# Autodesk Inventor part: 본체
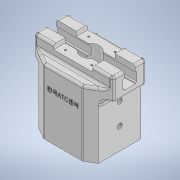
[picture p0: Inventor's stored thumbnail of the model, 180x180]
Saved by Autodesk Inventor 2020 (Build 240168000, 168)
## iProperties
Created: 2023-05
Part Number: 본체
Material: 일반
Document SubType Name: Modeling
Designer: oem
Density: 1 g/cm^3
Appearance: 기본값
Author: oem
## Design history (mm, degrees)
sketch "스케치1"
  geometry: L1 (0, 0)-(126.476, 0); L2 (25.019, -35)-(51, -20); L3 (51, -20)-(51, 20); L4 (25.019, 35)-(51, 20); L5 (0, 0)-(0, -35); L6 (0, -35)-(25.019, -35); L7 (0, 0)-(-126.476, 0); L8 (-25.019, -35)-(-51, -20); L9 (-51, -20)-(-51, 20); L10 (-25.019, 35)-(-51, 20); L11 (0, -35)-(-25.019, -35); L12 (25.019, 35)-(-25.019, 35)
  constraints: 24 end point, 6 symmetric about line, 2 horizontal, 1 vertical
  dimensions: "d7" = 30 deg angle of L1 L2; "d9" = 40 distance of L2.end L3.end; "d10" = 20 distance from line of L1 L2.end; "d11" = 20 distance from line of L1 L3.end; "d33" = 35 distance from line of L1 L2.start; "d34" = 51 distance from line of L1.start L3; "d39" = 35 distance of L1.start L5.end
extrude "돌출1" new body sketch "스케치1" distance "d12" = 29; taper "d13" = 0 deg
sketch "스케치5"
  geometry: L1 (51, 20)-(25.019, 35) reference; L2 (25.019, 35)-(-25.019, 35) reference; L3 (-25.019, 35)-(-51, 20) reference; L4 (-51, -20)-(-25.019, -35) reference; L5 (-25.019, -35)-(25.019, -35) reference; L6 (25.019, -35)-(51, -20) reference; L7 (74.204, -22)-(-74.204, -22); L8 (-74.204, -22)-(-74.204, 22); L9 (-74.204, 22)-(74.204, 22); L10 (74.204, 22)-(74.204, -22); L11 (74.204, -22)-(-74.204, 22); L12 (-74.204, -22)-(74.204, 22); 5 further points
  constraints: 12 end point, 2 midpoint, 2 parallel, 1 horizontal, 1 perpendicular
  dimensions: "d40" = 44 distance of L7.end L8.end; "d41" = 148.40766 distance of L8.end L9.end
extrude "돌출4" cut sketch "스케치5" distance "d42" = 15; taper "d43" = 0 deg
sketch "스케치6"
  geometry: L1 (0, 29)-(40, 29) reference; L2 (20, 29)-(12.8, 29); L3 (12.8, 29)-(12.8, 21.482); L4 (20, 21)-(11, 21); L5 (11, 21)-(11, 10); L6 (11, 21)-(12.8, 21.482); L7 (11, 21)-(14.021, 21); L8 (20, 8)-(12.8, 8); L9 (11, 15.5)-(18.681, 15.5); L10 (11, 10)-(12.8, 9.518); L11 (12.8, 8)-(12.8, 9.518); L12 (20, 8)-(20, 29); L13 (20, 29)-(27.2, 29); L14 (27.2, 29)-(27.2, 21.482); L15 (29, 21)-(29, 10); L16 (29, 10)-(27.2, 9.518); L17 (20, 8)-(27.2, 8); L18 (29, 21)-(27.2, 21.482); L19 (27.2, 8)-(27.2, 9.518); 1 further point
  constraints: 36 end point, 7 symmetric about line, 4 horizontal, 2 midpoint, 2 vertical, 1 perpendicular, 1 point on line
  dimensions: "d44" = 7.2 distance of L2.start L2.end; "d48" = 8 distance from line of L1 L4.end; "d49" = 11 distance of L4.end L5.end; "d50" = 9 horizontal distance of L4.end L2.start; "d51" = 15 deg angle of L7 L6; "d52" = 7.2 distance of L8.start L8.end; "d53" = 21 distance between parallel lines of L8 L1
extrude "돌출5" cut sketch "스케치6" extent not by distance; stored distance "d54" = 0; taper "d55" = 0 deg
sketch "스케치7"
  geometry: L1 (47.536, 22)-(-47.536, 22) reference; L2 (-25, -22)-(25, -22); L3 (25, -22)-(25, 22); L4 (25, 22)-(-25, 22); L5 (-25, 22)-(-25, -22); L6 (-25, -22)-(25, 22); L7 (25, -22)-(-25, 22); 2 further points
  constraints: 12 end point, 2 midpoint, 2 parallel, 1 horizontal, 1 perpendicular, 1 point on line
  dimensions: "d56" = 50 distance of L4.end L3.end
extrude "돌출6" cut sketch "스케치7" distance "d57" = 6; taper "d58" = 0 deg
sketch "스케치15"
  geometry: L1 (0, 0)-(29, 0); L2 (10.392, -6)-(29, -6); L3 (10.392, 6)-(29, 6); L4 (0, 0)-(0, -29.09); L5 (-10.392, -6)-(-29, -6); L6 (-10.392, 6)-(-29, 6); A1 r 6 centre (29, 0) between (29, -6) and (29, 6); A2 r 6 centre (-29, 0) between (-29, 6) and (-29, -6); A3 r 12 centre (0, 0) between (10.392, 6) and (-10.392, 6); A4 r 12 centre (0, 0) between (-10.392, -6) and (10.392, -6); 1 further point
  constraints: 12 end point, 8 point on circle, 5 symmetric about line, 4 centre point, 2 coincident, 2 parallel, 1 horizontal, 1 vertical, 1 other
  dimensions: "d116" = 29 distance of L1.start L1.end; "d117" = 6 distance between parallel lines of L1 L2; "d118" = 6 distance between parallel lines of L1 L3; "d120" = 6 radius of A1; "d121" = 12 radius of A4; "d122" = 12 radius of A3
extrude "돌출8" cut sketch "스케치15" distance "d114" = 30; taper "d115" = 0 deg
sketch "스케치18"
  geometry: L1 (51, -20)-(25.019, -35) reference; L2 (-25.019, -35)-(-51, -20) reference; L3 (25.019, -35)-(-25.019, -35) reference; L4 (0, 0)-(40, 0); L5 (40, 0)-(40, -26.351); L6 (25.019, -35)-(47.536, -22) reference; L7 (40, -26.351)-(25.019, -35); L8 (0, -35)-(0, 0); L9 (0, -35)-(25.019, -35); L10 (-25.019, -35)-(-38.01, -27.5); L11 (-25.019, -35)-(0, -35); L12 (-25.019, 35)-(0, 35); L13 (-25.019, 35)-(-38.01, 27.5); L14 (0, 35)-(25.019, 35); L15 (40, 26.351)-(25.019, 35); L16 (40, 0)-(40, 26.351); L17 (-51, 20)-(-25.019, 35) reference; L18 (0, 0)-(-40, 0); L19 (-40, 0)-(-40, 26.351); L20 (-38.01, 27.5)-(-40, 26.351); L21 (-40, 0)-(-40, -26.351); L22 (-38.01, -27.5)-(-40, -26.351); A1 r 12 centre (0, 0) between (-10.392, -6) and (10.392, -6) reference; A2 r 12 centre (0, 0) between (10.392, 6) and (-10.392, 6) reference
  constraints: 34 end point, 5 collinear, 3 point on line, 3 symmetric about line, 2 horizontal, 2 midpoint, 2 perpendicular, 2 vertical
  dimensions: "d136" = 40 distance of L4.start L4.end; "d254" = 40 distance of L18.start L18.end
extrude "돌출9" join sketch "스케치18" distance "d138" = 70; taper "d139" = 0 deg
node "작업 평면2"
sketch "스케치26"
  geometry: C1 r 10 at (0, 0); 1 further point
  constraints: 1 centre point, 1 coincident
  dimensions: "d180" = 20 diameter of C1
extrude "돌출10" cut sketch "스케치26" stored distance "d181" = 3.2; taper "d182" = 0 deg
sketch "스케치27"
  geometry: A1 r 12 centre (0, 0) between (9.6, 7.2) and (-9.6, 7.2) reference; 1 further point
  dimensions: "d184" = 17 horizontal distance of A1.centre point (-17, 15); "d185" = 15 vertical distance of A1.centre point (-17, 15)
hole "구멍11" sketch "스케치27" at (-17, 15) diameter "d186" = 2.459; stored, may be unused: countersink angle "d190" = 82 deg, drill point angle "d192" = 118 deg; dims "d187" = 6, "d188" = 3.023, "d189" = 2, "d191" = 8
fillet "모깎기2" dims "d232" = 3
fillet "모깎기3" dims "d233" = 3
fillet "모깎기4" dims "d234" = 3
sketch "스케치31"
  geometry: L1 (25.715, -34.598)-(40, -26.351) reference; L2 (40, -26.351)-(40, 26.351) reference; L3 (40, 26.351)-(25.715, 34.598) reference; L4 (38, 31.43)-(38, -34.903); 2 further points
  constraints: 2 end point, 1 vertical
  dimensions: "d235" = 2 distance between parallel lines of L2 L4
extrude "돌출11" cut sketch "스케치31" distance "d236" = 64; taper "d237" = 0 deg
fillet "모깎기5" dims "d248" = 3
sketch "스케치34"
  geometry: 2 further points
  constraints: 1 coincident
hole "구멍16" sketch "스케치34" at (0, 0) diameter "d255" = 60; stored, may be unused: countersink angle "d259" = 90 deg, drill point angle "d261" = 0 deg; dims "d256" = 9, "d257" = 17.3, "d258" = 2, "d260" = 5.8
sketch "스케치35"
  geometry: C1 r 30 at (0, 0) reference; 2 further points
  constraints: 1 coincident
hole "구멍17" sketch "스케치35" at (0, 0) diameter "d262" = 63; stored, may be unused: countersink angle "d266" = 90 deg, drill point angle "d268" = 0 deg; dims "d263" = 9, "d264" = 17.3, "d265" = 2, "d267" = 2.2
sketch "스케치36"
  geometry: C1 r 30 at (0, 0) reference; 2 further points
  constraints: 1 coincident
hole "구멍18" sketch "스케치36" at (0, 0) diameter "d269" = 60; stored, may be unused: countersink angle "d273" = 90 deg, drill point angle "d275" = 0 deg; dims "d270" = 9, "d271" = 17.3, "d272" = 2, "d274" = 6
sketch "스케치37"
  geometry: C1 r 30 at (0, 0) reference; 2 further points
  constraints: 1 coincident
hole "구멍19" sketch "스케치37" at (0, 0) diameter "d276" = 50; stored, may be unused: countersink angle "d280" = 90 deg, drill point angle "d282" = 0 deg; dims "d277" = 9, "d278" = 17.3, "d279" = 2, "d281" = 45
chamfer "모따기4" distance "d283" = 2; stored, may be unused: second distance "d284" = 2, angle "d285" = 20 deg
sketch "스케치39"
  geometry: C1 r 25 at (0, 0) reference; 2 further points
  constraints: 1 coincident
hole "구멍20" sketch "스케치39" at (0, 0) diameter "d286" = 16; stored, may be unused: countersink angle "d290" = 90 deg, drill point angle "d292" = 0 deg; dims "d287" = 9, "d288" = 17.3, "d289" = 2, "d291" = 45
sketch "스케치40"
  geometry: L1 (55.011, 0)-(0, 0) reference; L2 (-7.494, 81)-(-7.494, 0) reference; 2 further points
  dimensions: "d293" = 28 distance from line of L1 point (27.506, 28); "d294" = 35 distance from line of point (27.506, 28) L2
hole "구멍21" sketch "스케치40" at (27.506, 28) diameter "d295" = 4; stored, may be unused: countersink angle "d299" = 90 deg, drill point angle "d301" = 0 deg; dims "d296" = 9, "d297" = 17.3, "d298" = 2, "d300" = 45
sketch "스케치41"
  geometry: C1 r 2 at (27.506, 28) reference; 2 further points
  constraints: 1 coincident
hole "구멍22" sketch "스케치41" at (27.506, 28) diameter "d302" = 6.647; stored, may be unused: countersink angle "d306" = 90 deg, drill point angle "d308" = 118 deg; dims "d303" = 9, "d304" = 17.3, "d305" = 2, "d307" = 11
sketch "스케치42"
  geometry: L1 (-15.785, 73)-(-15.785, 0) reference; L2 (70.947, 99)-(49.215, 99) reference; 2 further points
  constraints: 1 other
  dimensions: "d312" = 40 distance from line of L1 point (24.215, 59); "d313" = 40 distance from line of point (24.215, 59) L2
feature "엠보싱1" sketch "스케치42" dims "d7" = 30 deg, "d9" = 40, "d10" = 20, "d11" = 20, "d33" = 35, "d34" = 51, "d39" = 35, "d314" = 0.5, "d315" = 0
chamfer "모따기5" distance "d316" = 1; stored, may be unused: second distance "d317" = 2, angle "d318" = 20 deg
node "솔리드1"
pattern_linear "직사각형 패턴1" dims "d195" = 34, "d198" = 30
pattern_linear "직사각형 패턴4" dims "d311" = 28
feature "A9D066F2-1C7D-4E18-AEED-F7BC21143FA4" dims "d186" = 2.459, "d187" = 6, "d188" = 3.023, "d189" = 2, "d190" = 82 deg, "d191" = 8, "d192" = 118 deg
other parameters: "d179" = -5
